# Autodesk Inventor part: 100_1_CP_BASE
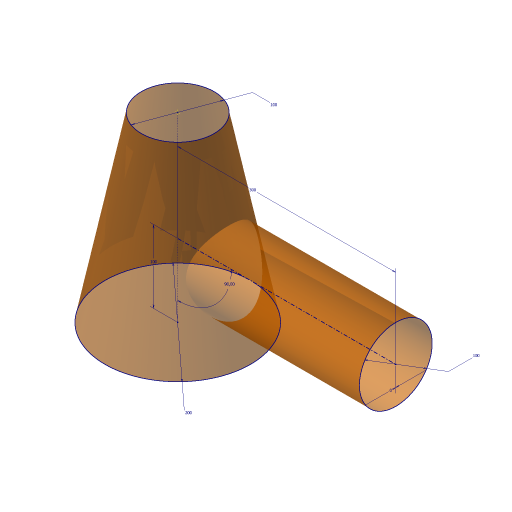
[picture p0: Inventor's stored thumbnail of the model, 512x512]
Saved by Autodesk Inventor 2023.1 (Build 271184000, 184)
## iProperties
Company: Fabian Stasiak CAD Consulting
Category: Autodesk® Inventor® Tutorial Series
Created: 2010-04
Part Number: 100_1_CP_BASE
Document SubType Name: Modeling
Designer: F.Stasiak
Density: 1 g/cm^3
Material: Ogólny
Appearance: Domyślna
Catalog Web Link: www.expertbooks.eu
CONE_DIA_1: 200,000 mm
CONE_HEIGHT: 250,000 mm
COEN_DIA_2: 100,000 mm
Author: F.Stasiak
Subject: Sheet Metal Design. Basic and Advanced techniques
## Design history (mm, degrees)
sketch "Szkic1"
  geometry: C1 r 100 at (0, 0); 1 further point
  constraints: 1 centre point, 1 coincident
  dimensions: "CONE_DIA_1" = 200 diameter of C1
node "Płaszczyzna konstrukcyjna1"
sketch "Szkic2"
  geometry: C1 r 50 at (0, 0); 1 further point
  constraints: 1 centre point, 1 coincident
  dimensions: "COEN_DIA_2" = 100 diameter of C1
sketch "Szkic3"
  geometry: L1 (0, 250)-(0, 0); L2 (0, 100)-(-300, 100)
  constraints: 4 end point, 1 point on line, 1 vertical
  dimensions: "PIPE_AXIS_ELEV" = 100 distance of L2.start L1.end; "PIPE_ANGLE" = 90 deg angle of L2 L1; "PIPE_LENGTH" = 300 distance of L2.start L2.end
node "Płaszczyzna konstrukcyjna2"
sketch "Szkic4"
  geometry: C1 r 50 at (0, 0); 1 further point
  constraints: 1 centre point, 1 coincident
  dimensions: "PIPE_DIA" = 100 diameter of C1; "PIPE_OFFSET" = 0 distance of point (0, 0) C1.centre
feature "PowWyciągnięciaZłożonego1" dims "d8" = 0, "d9" = 90 deg, "d10" = 0, "d11" = 90 deg
feature "PowWyciągnięciaProstego1" dims "d12" = 10, "d13" = 0
feature "Utnij1"
body "Srf1"
body "Srf2"
other parameters: "CONE_HEIGHT" = 250
